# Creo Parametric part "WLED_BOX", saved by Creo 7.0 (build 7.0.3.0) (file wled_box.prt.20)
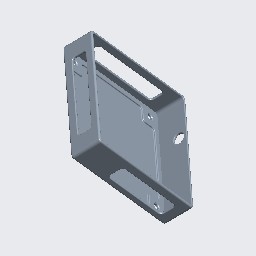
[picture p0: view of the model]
Units: millimeter Kilogram Sec (mmKs); MM, KILOGRAM, SECS

Created from: XX_SOLID_PART_MMKS_ABS.PRT

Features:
  1. coordinate system
  2. datum plane "RIGHT"
  3. datum plane "TOP"
  4. datum plane "FRONT"
  5. extrusion "Extrude 1"
  6. extrusion "Extrude 2"
  7. extruded cut "Extrude 3"
  8. extruded cut "Extrude 4"
  9. extruded cut "Extrude 5"
  10. round "Round 1"
  11. round "Round 2"
  12. extruded cut "Extrude 6"
  13. extruded cut "Extrude 7"
  14. round "Round 3"
  15. round "Round 4"
  16. round "Round 5"
  17. round "Round 6"
  18. chamfer "Chamfer 1"
  19. extruded cut "Extrude 8"
  20. round "Round 7"

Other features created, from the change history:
  round "Round 3" (2 times)
  extruded cut "Extrude 6"
  extruded cut "Extrude 7"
